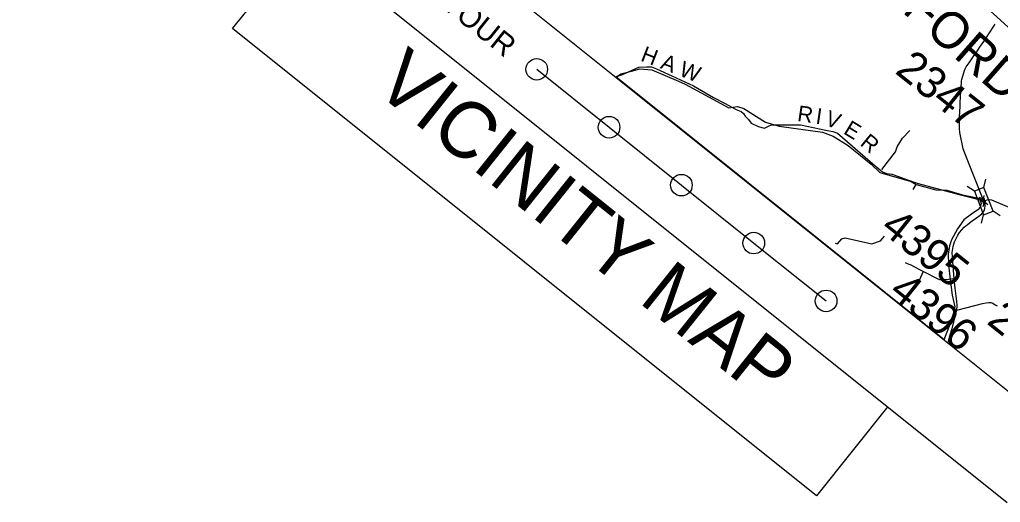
# Model space of a CAD drawing. Extents: x 1732765 to 1738218, y 913652 to 917906.
# Drawn here: x 1733949 to 1734585, y 916444 to 916757 of the extents above; entities that cross this region are included whole.
import ezdxf

# ---------------------------------------------------------------- set-up
doc = ezdxf.new("R2010")
doc.units = 0
for name, color, linetype in [('Old_Level_24', 7, 'Continuous'), ('Old_Level_32', 7, 'Continuous'), ('Old_Level_48', 7, 'Continuous'), ('Old_Level_49', 7, 'Continuous'), ('Old_Level_50', 7, 'Continuous'), ('Old_Level_52', 7, 'Continuous'), ('Old_Level_57', 7, 'Continuous'), ('Old_Level_59', 7, 'Continuous'), ('Old_Level_8', 7, 'Continuous'), ('Sheet Title CELL', 7, 'Continuous')]:
    doc.layers.add(name, color=color, linetype=linetype)

msp = doc.modelspace()

# ---------------------------------------------------------------- linework, layer by layer
at = {"layer": 'Old_Level_24'}
for p, q in [((1734284.72, 916724.46), (1734331.64, 916686.91)), ((1734331.64, 916686.91), (1734378.57, 916649.35)), ((1734378.57, 916649.35), (1734425.49, 916611.8)), ((1734425.49, 916611.8), (1734472.42, 916574.25))]:
    msp.add_line(p, q, dxfattribs=at)
for centre in [(1734284.72, 916724.46), (1734331.64, 916686.91), (1734378.57, 916649.35), (1734425.49, 916611.8), (1734472.42, 916574.25)]:
    msp.add_circle(centre, 7.01, dxfattribs=at)
at = {"layer": 'Old_Level_32'}
for points in [[(1734574.64, 916639), (1734564.01, 916666.3), (1734561.27, 916672.9), (1734559.08, 916683.54), (1734558.98, 916686.19), (1734558.97, 916689.1), (1734558.96, 916691.08), (1734559.02, 916693.47), (1734559.28, 916700.62), (1734559.44, 916702.65), (1734559.67, 916706.61), (1734559.86, 916710.07), (1734560.22, 916715.95), (1734560.29, 916717.02), (1734560.53, 916717.93), (1734560.81, 916719.41), (1734562.15, 916723.66), (1734562.63, 916724.69), (1734563.28, 916725.99), (1734563.98, 916727.03), (1734565.13, 916728.75), (1734567.78, 916732.54), (1734569.32, 916734.65), (1734570.53, 916736.45), (1734571.95, 916738.59), (1734573.02, 916740.11), (1734575.93, 916744.3), (1734577.63, 916746.82), (1734582.06, 916753.72)], [(1734555.53, 916588.52), (1734554.37, 916602.64), (1734554.18, 916605.77), (1734554.78, 916609.62), (1734555.79, 916612.51), (1734557.81, 916616.93), (1734558.92, 916618.63), (1734561.89, 916622.03), (1734564.07, 916623.93), (1734567.11, 916626.27), (1734571.58, 916629.29), (1734573.39, 916630.7), (1734574.86, 916632.67), (1734575.46, 916634.16), (1734575.56, 916635.94), (1734575.37, 916637.21), (1734574.64, 916639)], [(1734535.46, 916593.25), (1734532.84, 916594.69), (1734530.34, 916595.93), (1734527.59, 916597.38), (1734525.17, 916598.38), (1734524.02, 916598.96)], [(1734535.46, 916593.25), (1734533.55, 916589.4), (1734532.29, 916586.66), (1734531.21, 916584.47), (1734530.61, 916582.98)], [(1734555.53, 916588.52), (1734551.75, 916588.24), (1734548.85, 916588.01), (1734547.32, 916587.91), (1734546.22, 916588.01), (1734545, 916588.38), (1734541.72, 916590), (1734539.16, 916591.38), (1734535.46, 916593.25)], [(1734557.3, 916568.18), (1734557.35, 916571.01), (1734557.14, 916574.08), (1734556.86, 916577.34), (1734556.14, 916582.6), (1734555.53, 916588.52)], [(1734557.3, 916568.18), (1734568.89, 916571.34), (1734573.92, 916572.53), (1734576.25, 916572.97), (1734578.02, 916573.19), (1734579.2, 916573.31), (1734580.49, 916572.84), (1734582, 916571.79), (1734583.42, 916571.12)], [(1734551.68, 916546.97), (1734551.87, 916548.07), (1734552.76, 916551.58), (1734554.17, 916556.3), (1734556.37, 916564.84), (1734557.3, 916568.18)]]:
    msp.add_lwpolyline(points, dxfattribs=at)
at = {"layer": 'Old_Level_48'}
for points in [[(1734336.02, 916719.57), (1734340.34, 916721.16), (1734350.98, 916725.83), (1734355.98, 916726.14), (1734359.11, 916726.1), (1734362.52, 916724.87), (1734372.33, 916720.27), (1734386.31, 916713.82), (1734399.35, 916706.25), (1734406.85, 916702.29), (1734414.15, 916698.49), (1734417.41, 916697.07), (1734418.92, 916695.83), (1734419.96, 916694.03), (1734422.07, 916691.98), (1734423.86, 916689.55), (1734428.41, 916687.39), (1734432.51, 916686.23), (1734434.97, 916687.68), (1734436.96, 916688.57), (1734439.06, 916688.42), (1734443.51, 916688.36), (1734455.9, 916688.48), (1734472.15, 916684.93), (1734476.82, 916684.04), (1734479.88, 916682.99), (1734504.31, 916661.9), (1734509, 916658.04), (1734511.53, 916656.94), (1734515.08, 916656.48), (1734519.27, 916654.99), (1734524.58, 916653.08), (1734532.13, 916650.31), (1734558.7, 916643.18), (1734566.44, 916641.24), (1734572.15, 916639.9)], [(1734549.06, 916549.08), (1734336.02, 916719.57)], [(1734572.15, 916639.9), (1734572.94, 916637.41), (1734572.44, 916634.98), (1734570.76, 916633.35), (1734566.64, 916630.57), (1734561.69, 916626.78), (1734557.62, 916620.92), (1734553.76, 916613.9), (1734552.54, 916609.96), (1734551.69, 916604.5), (1734551.79, 916597.72), (1734552.97, 916588.24), (1734554.27, 916578.04), (1734555.82, 916570.33), (1734554.56, 916565.3), (1734552.75, 916558.98), (1734549.15, 916550.07), (1734549.06, 916549.08)]]:
    msp.add_lwpolyline(points, dxfattribs=at)
at = {"layer": 'Old_Level_49'}
for points in [[(1734336.02, 916719.57), (1734340.34, 916721.16), (1734350.98, 916725.83), (1734355.98, 916726.14), (1734359.11, 916726.1), (1734362.52, 916724.87), (1734372.33, 916720.27), (1734386.31, 916713.82), (1734399.35, 916706.25), (1734406.85, 916702.29), (1734414.15, 916698.49), (1734417.41, 916697.07), (1734418.92, 916695.83), (1734419.96, 916694.03), (1734422.07, 916691.98), (1734423.86, 916689.55), (1734428.41, 916687.39), (1734432.51, 916686.23), (1734434.97, 916687.68), (1734436.96, 916688.57), (1734439.06, 916688.42), (1734443.51, 916688.36), (1734455.9, 916688.48), (1734472.15, 916684.93), (1734476.82, 916684.04), (1734479.88, 916682.99), (1734504.31, 916661.9), (1734509, 916658.04), (1734511.53, 916656.94), (1734515.08, 916656.48), (1734519.27, 916654.99), (1734524.58, 916653.08), (1734532.13, 916650.31), (1734558.7, 916643.18), (1734566.44, 916641.24), (1734572.15, 916639.9)], [(1734549.06, 916549.08), (1734336.02, 916719.57)], [(1734572.15, 916639.9), (1734572.94, 916637.41), (1734572.44, 916634.98), (1734570.76, 916633.35), (1734566.64, 916630.57), (1734561.69, 916626.78), (1734557.62, 916620.92), (1734553.76, 916613.9), (1734552.54, 916609.96), (1734551.69, 916604.5), (1734551.79, 916597.72), (1734552.97, 916588.24), (1734554.27, 916578.04), (1734555.82, 916570.33), (1734554.56, 916565.3), (1734552.75, 916558.98), (1734549.15, 916550.07), (1734549.06, 916549.08)]]:
    msp.add_lwpolyline(points, dxfattribs=at)
at = {"layer": 'Old_Level_50'}
for p, q in [((1734574.72, 916647.84), (1734576.1, 916653.26)), ((1734568.6, 916645.46), (1734563.92, 916648.52)), ((1734573.13, 916640.62), (1734571.96, 916641.38)), ((1734574.66, 916641.21), (1734575.01, 916642.57)), ((1734574.27, 916635.44), (1734574.62, 916636.79)), ((1734577.32, 916636.62), (1734576.15, 916637.39)), ((1734585.36, 916629.49), (1734580.68, 916632.54)), ((1734573.17, 916624.75), (1734574.56, 916630.16))]:
    msp.add_line(p, q, dxfattribs=at)
msp.add_lwpolyline([(1734568.6, 916645.46), (1734574.56, 916630.16), (1734580.68, 916632.54), (1734574.72, 916647.84)], close=True, dxfattribs=at)
msp.add_lwpolyline([(1734573.13, 916640.62), (1734574.62, 916636.79), (1734576.15, 916637.39), (1734574.66, 916641.21), (1734573.13, 916640.62)], dxfattribs=at)
at = {"layer": 'Old_Level_52'}
msp.add_lwpolyline([(1734732.93, 916622.27), (1734723.88, 916630.49), (1734583.09, 916758.4), (1734358.65, 916958.62), (1734222.3, 917078.43)], dxfattribs=at)
at = {"layer": 'Old_Level_59'}
msp.add_line((1734528.84, 916646.55), (1734530.94, 916649.73), dxfattribs=at)
for points in [[(1734335.98, 916719.6), (1734337.28, 916720.27), (1734339.32, 916721.49), (1734346.15, 916723.31), (1734351.62, 916724.79), (1734359.48, 916724.1), (1734376.7, 916716.76), (1734380.91, 916714.86), (1734409.36, 916699.5)], [(1734409.36, 916699.5), (1734414.99, 916700.4), (1734419.13, 916699.12), (1734433.21, 916690.29), (1734441.92, 916687.68), (1734470.09, 916683.64), (1734476.95, 916681.11), (1734486.67, 916675.16), (1734501.65, 916662.85), (1734507.26, 916657.5)], [(1734508.62, 916659.47), (1734517.4, 916670.87), (1734518.6, 916674.27), (1734521.93, 916679.86), (1734526.68, 916684.87)], [(1734507.26, 916657.5), (1734527.67, 916651.67), (1734530.94, 916649.73)], [(1734530.94, 916649.73), (1734543.55, 916646.27), (1734550.78, 916646.12)], [(1734550.78, 916646.12), (1734560.78, 916642.96), (1734568.35, 916641.56), (1734571.28, 916640.85), (1734572.1, 916640.44), (1734572.69, 916639.89), (1734573.06, 916639.26), (1734573.35, 916638.99), (1734573.92, 916638.85), (1734574.64, 916639), (1734576.87, 916639.87), (1734578.12, 916639.95), (1734579.73, 916639.73), (1734581.19, 916639.24), (1734594.97, 916633.41)], [(1734478.33, 916611.67), (1734479.85, 916611.23), (1734482.65, 916614.56), (1734484.82, 916615.19), (1734502.02, 916611.36), (1734507.62, 916613.16), (1734510.21, 916616.23)]]:
    msp.add_lwpolyline(points, dxfattribs=at)
at = {"layer": 'Sheet Title CELL'}
for p, q in [((1734091.57, 916915.07), (1734625.37, 916487.87)), ((1734091.57, 916915.07), (1734625.37, 916487.87)), ((1734091.57, 916915.07), (1734625.37, 916487.87)), ((1734056.15, 916870.82), (1734589.95, 916443.62)), ((1734087.51, 916751), (1734133.72, 916808.74)), ((1734466.17, 916447.95), (1734087.51, 916751)), ((1734512.39, 916505.7), (1734466.17, 916447.95))]:
    msp.add_line(p, q, dxfattribs=at)

# ---------------------------------------------------------------- texts
at = {"layer": 'Old_Level_24'}
msp.add_text('DETOUR', height=14, rotation=321.32968, dxfattribs=at).set_placement((1734202.38, 916781.12))
at = {"layer": 'Old_Level_52'}
msp.add_text('GUILFORD  COUNTY', height=23.786, rotation=318.72172, dxfattribs=at).set_placement((1734465.36, 916810.93))
at = {"layer": 'Old_Level_57'}
for s, height, rotation, p in [('H A W', 10.261, 338.79719, (1734351.54, 916730.23)), ('R', 10.26, 351.83908, (1734453.34, 916691.02)), ('I', 10.26, 351.83908, (1734465.25, 916689.31)), ('V', 10.26, 339.73899, (1734471.01, 916688.55)), ('E', 10.26, 328.50444, (1734483.06, 916683.14)), ('R', 10.26, 320.5855, (1734493.84, 916675.64))]:
    msp.add_text(s, height=height, rotation=rotation, dxfattribs=at).set_placement(p)
at = {"layer": 'Old_Level_8'}
for s, p in [('2347', (1734516.43, 916722.46)), ('4395', (1734506.74, 916619.94)), ('4396', (1734512.22, 916578.41)), ('2304', (1734575.89, 916559.99))]:
    msp.add_text(s, height=20.505, rotation=321.32968, dxfattribs=at).set_placement(p)
at = {"layer": 'Sheet Title CELL'}
for s, height, rotation, p in [('TIP PROJECT:', 49.9999, 51.32968, (1733836.74, 916691.55)), ('VICINITY MAP', 36.621, 321.32968, (1734178.1, 916711.45))]:
    msp.add_text(s, height=height, rotation=rotation, dxfattribs=at).set_placement(p)

doc.saveas('drawing.dxf')
